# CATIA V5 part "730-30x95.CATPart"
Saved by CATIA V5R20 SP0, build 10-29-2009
Part number: 730-30x95
Definition: NONE
Nomenclature: 730-30x95
Source: Unknown
Description: 730-30x95
Bounding box of the stored display mesh (mm): x -19 to 19, y -18.312 to 18.312, z 0 to 95
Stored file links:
  C:\Users\Utente\Desktop\IO LAVORO\3D X SITO CF\X SITO\730\730-30x95.CATPart
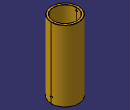
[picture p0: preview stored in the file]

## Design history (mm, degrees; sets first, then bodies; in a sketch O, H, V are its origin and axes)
Body1 "730-30x95" (main body)
  Solid1: solid without history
